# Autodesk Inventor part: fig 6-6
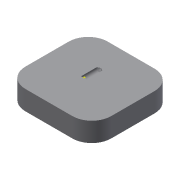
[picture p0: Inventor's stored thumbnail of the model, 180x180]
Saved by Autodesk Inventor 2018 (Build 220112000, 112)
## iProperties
Created: 2004-05
Part Number: fig 6-6
Document SubType Name: Modeling
Designer: CADCIM Technologies
Manufacturer: Standard
Standards Organization: Custom
Density: 1 g/cm^3
Material: Generic
Appearance: Default
Author: CADCIM Technologies
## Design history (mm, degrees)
sketch "Sketch1"
  geometry: L1 (0, 0)-(44.293, 0); L2 (44.293, 0)-(44.293, 42.442); L3 (44.293, 42.442)-(0, 42.442); L4 (0, 42.442)-(0, 0)
  constraints: 8 end point, 2 parallel, 1 horizontal, 1 perpendicular
extrude "Extrusion1" new body sketch "Sketch1" distance "d0" = 10; taper "d1" = 0 deg
fillet "Fillet1" dims "d2" = 10
sketch "Sketch2"
  geometry: 1 further point
sketch "Sketch3"
  geometry: L1 (10, 42.442)-(34.293, 42.442) reference; L2 (0, 10)-(0, 32.442) reference; L3 (34.293, 0)-(10, 0) reference; L4 (44.293, 32.442)-(44.293, 10) reference; A1 r 10 centre (34.293, 32.442) between (44.293, 32.442) and (34.293, 42.442) reference; A2 r 10 centre (10, 32.442) between (10, 42.442) and (0, 32.442) reference; A3 r 10 centre (10, 10) between (0, 10) and (10, 0) reference; A4 r 10 centre (34.293, 10) between (34.293, 0) and (44.293, 10) reference; 1 further point
workpoint "Work Point1"
hole "Hole4" diameter "d33" = 3; stored, may be unused: countersink angle "d37" = 90 deg, drill point angle "d39" = 118 deg; dims "d31" = 10, "d32" = 10, "d34" = 6, "d35" = 4, "d36" = 2, "d38" = 8
body "Solid1"
